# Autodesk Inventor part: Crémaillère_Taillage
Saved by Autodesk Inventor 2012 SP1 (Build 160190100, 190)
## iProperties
Created: 2014-12
Part Number: Crémaillère_Taillage
Material: Default
Document SubType Name: Modeling
Designer: Bruno
Density: 1 g/cm^3
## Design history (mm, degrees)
node "Crémaillère_Taillage1"
node "Crémaillère_Taillage"
node "Base1"
